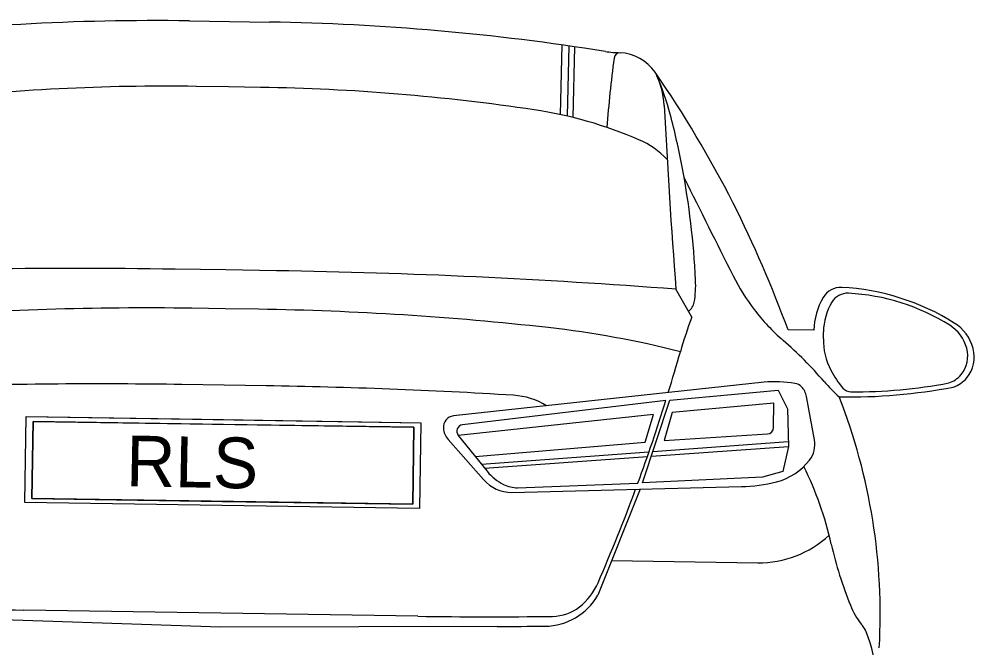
# Model space of a CAD drawing. Extents: x 10133 to 81668, y 4692 to 11018.
# Drawn here: x 11865.4 to 11963.4, y 9346.2 to 9410.6 of the extents above; entities that cross this region are included whole.
import ezdxf

# ---------------------------------------------------------------- set-up
doc = ezdxf.new("R2010")
doc.units = 0
doc.layers.add('Cell', color=7, linetype='Continuous')
doc.layers.add('SheetBorder', color=7, linetype='Continuous')

msp = doc.modelspace()

# ---------------------------------------------------------------- linework, layer by layer
at = {"layer": 'Cell'}
for p, q in [((11920.87, 9400.786), (11921.051, 9407.918)), ((11921.59, 9400.625), (11921.771, 9407.816)), ((11922.156, 9400.489), (11922.334, 9407.734)), ((11934.324, 9380.04), (11932.695, 9382.908)), ((11946.834, 9378.708), (11944.183, 9378.749)), ((11947.799, 9377.851), (11947.809, 9378.55)), ((11941.729, 9373.402), (11909.893, 9369.942)), ((11946.88, 9367.512), (11946.075, 9371.935)), ((11931.663, 9371.52), (11910.823, 9369.03)), ((11865.998, 9361.074), (11866.128, 9369.874)), ((11866.128, 9369.874), (11886.345, 9369.562)), ((11866.836, 9369.379), (11866.72, 9361.498)), ((11886.338, 9369.079), (11866.836, 9369.379)), ((11905.84, 9368.779), (11886.338, 9369.079)), ((11886.345, 9369.562), (11906.562, 9369.251)), ((11906.562, 9369.251), (11906.432, 9360.452)), ((11905.723, 9360.898), (11905.84, 9368.779)), ((11910.393, 9367.949), (11913.361, 9364.272)), ((11931.492, 9367.411), (11942.088, 9368.096)), ((11909.354, 9367.533), (11912.981, 9363.421)), ((11930.334, 9366.293), (11944.204, 9367.313)), ((11912.772, 9365.002), (11929.933, 9366.264)), ((11930.176, 9365.809), (11944.215, 9366.798)), ((11913.092, 9364.606), (11929.765, 9365.78)), ((11916.474, 9362.581), (11928.793, 9363.059)), ((11915.875, 9362.107), (11939.409, 9362.704)), ((11929.019, 9362.44), (11924.696, 9351.609)), ((11886.215, 9360.763), (11865.998, 9361.074)), ((11866.72, 9361.498), (11886.221, 9361.198)), ((11886.221, 9361.198), (11905.723, 9360.898)), ((11906.432, 9360.452), (11886.215, 9360.763)), ((11926.105, 9355.14), (11941.074, 9354.91))]:
    msp.add_line(p, q, dxfattribs=at)
for points in [[(11882.841, 9410.385), (11886.947, 9410.322), (11891.053, 9410.259)], [(11890.139, 9403.577), (11886.848, 9403.628), (11883.557, 9403.678)], [(11891.754, 9384.804), (11886.571, 9384.884), (11881.389, 9384.964)], [(11889.927, 9380.859), (11886.513, 9380.912), (11883.098, 9380.964)], [(11890.707, 9373.024), (11886.397, 9373.09), (11882.087, 9373.156)], [(11929.283, 9363.078), (11932.059, 9371.568), (11943.172, 9372.595), (11944.128, 9370.677), (11944.215, 9366.798), (11943.663, 9364.242), (11941.557, 9363.67), (11929.283, 9363.078)], [(11942.701, 9368.749), (11942.738, 9371.241), (11932.316, 9370.296), (11931.492, 9367.411)], [(11912.128, 9365.799), (11929.552, 9367.25), (11930.388, 9370.09), (11910.393, 9367.949)], [(11906.236, 9349.44), (11886.052, 9349.751), (11865.869, 9350.061)], [(11914.381, 9348.392), (11886.031, 9348.329), (11857.696, 9349.265)]]:
    msp.add_lwpolyline(points, dxfattribs=at)
for centre, major_axis, start_param, end_param in [((11879.18, 9162.587), (1.612, -247.821), 3.120007, 3.261498), ((11887.392, 9162.461), (1.612, -247.821), 2.978516, 3.120007), ((11926.999, 9417.091), (0.065, -9.96), 6.120109, 6.27416), ((11926.979, 9406.493), (0.004, -0.638), 3.140474, 4.570017), ((11926.729, 9402.36), (0.031, -4.777), 2.182411, 3.08264), ((12035.006, 9391.504), (0.724, -111.223), 4.570017, 4.634219), ((11923.489, 9401.31), (0.053, -8.132), 1.615314, 2.053089), ((11834.491, 9337.024), (0.773, -118.896), 2.042534, 2.174295), ((11906.285, 9393.82), (0.176, -27.119), 1.825549, 1.979981), ((11880.341, 9186.016), (1.416, -217.683), 3.120007, 3.251156), ((11886.923, 9185.915), (1.416, -217.683), 2.988858, 3.120007), ((11911.769, 9357.129), (0.29, -44.622), 2.734832, 2.988858), ((12621.516, 9437.402), (4.559, -700.777), 4.756907, 4.783813), ((11857.889, 9380.7), (0.507, -77.931), 1.754888, 1.825549), ((11925.557, 9390.189), (0.057, -8.725), 2.323499, 2.734832), ((11853.69, 9379.879), (0.535, -82.268), 1.612544, 1.754888), ((13676.802, 10284.068), (12.878, -1979.514), 5.172147, 5.177831), ((11825.677, 9333.695), (0.835, -128.371), 1.922977, 2.033504), ((11871.304, 8702.525), (4.44, -682.503), 3.120007, 3.180922), ((11881.67, 8702.366), (4.44, -682.503), 3.059092, 3.120007), ((11924.474, 9383.339), (0.068, -10.39), 1.396134, 1.612544), ((11957.725, 9394.204), (0.142, -21.83), 5.177831, 5.364919), ((11949.571, 9380.984), (0.014, -2.119), 3.083943, 4.165968), ((11948.434, 9358.415), (0.161, -24.717), 2.582762, 3.083943), ((11953.482, 9378.606), (0.044, -6.744), 4.165968, 4.690803), ((11950.272, 9380.598), (0.012, -1.907), 3.083943, 4.165968), ((11949.249, 9360.286), (0.145, -22.245), 2.582762, 3.083943), ((11878.368, 9060.855), (2.083, -320.14), 3.120007, 3.214195), ((11885.197, 9060.75), (2.083, -320.14), 3.025819, 3.120007), ((11933.151, 9381.844), (0.01, -1.464), 0.60517, 1.396134), ((11957.288, 9393.86), (0.138, -21.269), 5.364919, 5.570378), ((11953.792, 9378.458), (0.039, -6.069), 4.165968, 4.690803), ((11970.422, 9365.683), (0.256, -39.325), 4.332271, 4.426951), ((11908.59, 9277.216), (0.666, -102.378), 2.889231, 3.025819), ((11958.69, 9375.825), (0.026, -3.991), 1.830697, 2.582762), ((11958.924, 9375.681), (0.029, -4.434), 1.830697, 2.582762), ((11954.349, 9377.751), (0.043, -6.645), 4.690803, 5.195439), ((11917.794, 9346.904), (0.263, -40.456), 2.280619, 2.428785), ((11959.64, 9376.088), (0.019, -2.992), 0.868626, 1.830697), ((11959.98, 9375.973), (0.022, -3.325), 0.868626, 1.830697), ((11758.169, 9427.359), (1.201, -184.605), 1.261729, 1.285358), ((11957.149, 9379.263), (0.064, -9.862), 5.195439, 5.421454), ((11959.87, 9375.893), (0.017, -2.688), 0.290491, 0.868626), ((11960.235, 9375.757), (0.019, -2.987), 0.290491, 0.868626), ((11873.609, 8799.433), (3.733, -573.777), 3.120007, 3.16484), ((11882.229, 8799.301), (3.733, -573.777), 3.075174, 3.120007), ((11942.693, 9358.967), (0.094, -14.468), 2.980494, 3.202621), ((11944.715, 9372.032), (0.008, -1.243), 2.379945, 2.993447), ((11944.228, 9371.59), (0.012, -1.904), 1.746734, 2.350337), ((11959.303, 9383.557), (0.1, -15.369), 5.422211, 5.567254), ((11950.449, 9429.836), (0.377, -57.948), 6.258811, 6.464055), ((11951.063, 9424.565), (0.339, -52.153), 6.268082, 6.464055), ((11915.614, 9364.678), (0.048, -7.392), 2.584625, 3.075174), ((11893.827, 9349.603), (0.395, -60.649), 1.508257, 1.940781), ((11950.635, 9373.52), (0.007, -1.107), 5.421454, 6.268082), ((11758.169, 9427.359), (1.201, -184.605), 1.208619, 1.257099), ((11910.016, 9368.779), (0.008, -1.17), 3.241933, 4.787449), ((11910.9, 9368.37), (0.004, -0.664), 3.252454, 5.39193), ((11910.797, 9368.843), (0.013, -1.965), 4.787449, 5.436302), ((11942.046, 9368.759), (0.004, -0.664), 0.057242, 1.549211), ((11944.383, 9367.015), (0.017, -2.581), 0.898902, 1.75794), ((11941.498, 9369.312), (0.041, -6.3), 0.238642, 0.898902), ((11917.201, 9367.461), (0.033, -5.034), 5.39193, 5.826812), ((11914.489, 9348.914), (0.231, -35.501), 1.788873, 2.027372), ((11915.877, 9366.049), (0.026, -3.942), 5.435788, 6.275832), ((11938.993, 9379.461), (0.109, -16.762), 0.018579, 0.238642), ((11916.537, 9366.066), (0.023, -3.485), 5.826812, 6.258127), ((11758.169, 9427.359), (1.201, -184.605), 1.14901, 1.204977), ((11941.232, 9365.637), (0.07, -10.728), 6.2616, 7.020005), ((11987.014, 9365.711), (0.26, -39.954), 4.930466, 5.095041), ((11918.985, 9355.426), (0.041, -6.351), 0.650241, 1.14901), ((11919.255, 9354.781), (0.041, -6.365), 0.001017, 1.042677), ((11873.172, 9844.273), (3.215, -494.258), 6.233227, 6.2616), ((11920, 9354.091), (0.03, -4.665), 0.006787, 0.650241), ((11957.669, 9353.508), (0.051, -7.784), 5.095041, 5.382013), ((11913.539, 9843.651), (3.215, -494.258), 6.2616, 6.289972), ((11912.159, 10299.907), (6.19, -951.497), 6.278956, 6.284202), ((11948.376, 9345.946), (0.028, -4.3), 1.884865, 2.240421), ((11931.234, 9340.175), (0.147, -22.62), 1.666626, 1.884865)]:
    msp.add_ellipse(centre, major_axis=major_axis, ratio=0.985916, start_param=start_param, end_param=end_param, dxfattribs=at)
at = {"layer": 'SheetBorder'}
for points in [[(11866.128, 9369.874), (11906.562, 9369.251), (11906.432, 9360.452), (11865.998, 9361.074)], [(11866.836, 9369.379), (11905.84, 9368.779), (11905.723, 9360.898), (11866.72, 9361.498)]]:
    msp.add_lwpolyline(points, close=True, dxfattribs=at)

# ---------------------------------------------------------------- texts
msp.add_text('RLS', height=5.1966, rotation=358.89312, dxfattribs=at).set_placement((11876.335, 9362.756))

doc.saveas('drawing.dxf')
